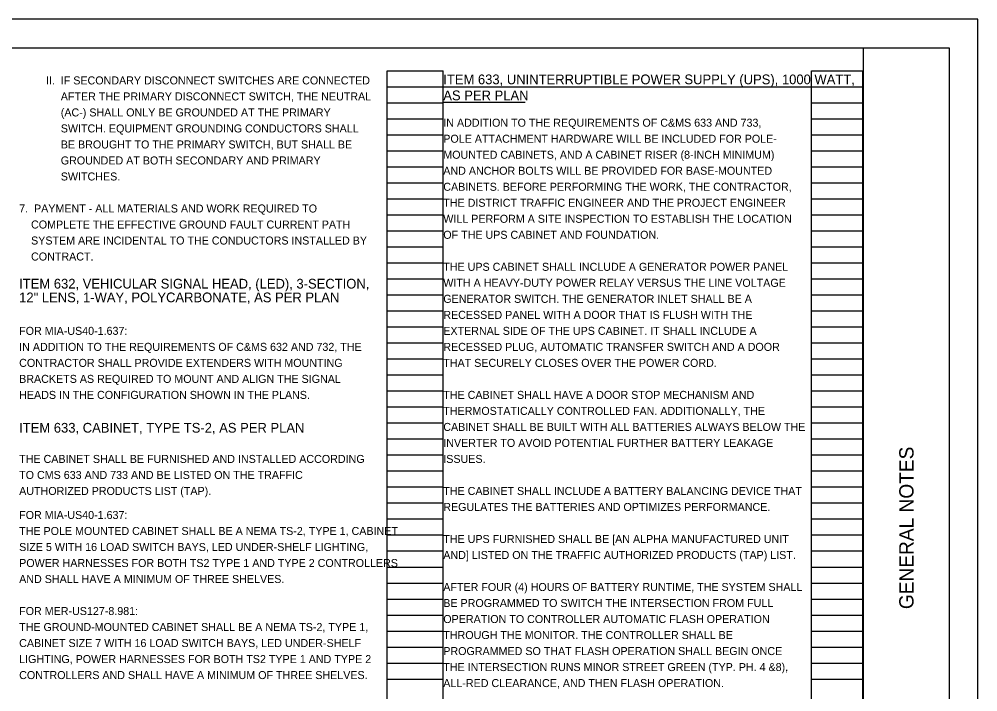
# Model space of a CAD drawing. Extents: x -57 to 90, y -15 to 48.
# Drawn here: x 72.92 to 89.69, y 35.74 to 47.51 of the extents above; entities that cross this region are included whole.
import ezdxf

# ---------------------------------------------------------------- set-up
doc = ezdxf.new("R2010")
doc.units = 0
for name, color, linetype in [('SH_Border', 7, 'Continuous'), ('SH_Cut_Line', 7, 'Continuous'), ('SH_Data', 7, 'Continuous'), ('SH_Text', 7, 'Continuous')]:
    doc.layers.add(name, color=color, linetype=linetype)

msp = doc.modelspace()

# ---------------------------------------------------------------- linework, layer by layer
at = {"layer": 'SH_Border'}
msp.add_line((87.688, 26.006), (87.688, 47.006), dxfattribs=at)
msp.add_lwpolyline([(57.188, 47.006), (89.188, 47.006), (89.188, 26.006), (57.188, 26.006)], close=True, dxfattribs=at)
at = {"layer": 'SH_Cut_Line'}
msp.add_lwpolyline([(55.688, 25.506), (89.688, 25.506), (89.688, 47.506), (55.688, 47.506)], close=True, dxfattribs=at)
at = {"layer": 'SH_Data'}
for p, q in [((79.356, 26.445), (79.356, 46.605)), ((79.356, 46.605), (80.336, 46.605)), ((80.336, 26.445), (80.336, 46.605)), ((86.776, 26.445), (86.776, 46.605)), ((86.776, 46.605), (87.676, 46.605)), ((87.676, 26.445), (87.676, 46.605)), ((79.356, 46.325), (80.336, 46.325)), ((86.776, 46.325), (87.676, 46.325)), ((79.356, 46.045), (80.336, 46.045)), ((86.776, 46.045), (87.676, 46.045)), ((79.356, 45.765), (80.336, 45.765)), ((86.776, 45.765), (87.676, 45.765)), ((79.356, 45.485), (80.336, 45.485)), ((86.776, 45.485), (87.676, 45.485)), ((79.356, 45.205), (80.336, 45.205)), ((86.776, 45.205), (87.676, 45.205)), ((79.356, 44.925), (80.336, 44.925)), ((86.776, 44.925), (87.676, 44.925)), ((79.356, 44.645), (80.336, 44.645)), ((86.776, 44.645), (87.676, 44.645)), ((79.356, 44.365), (80.336, 44.365)), ((86.776, 44.365), (87.676, 44.365)), ((79.356, 44.085), (80.336, 44.085)), ((86.776, 44.085), (87.676, 44.085)), ((79.356, 43.805), (80.336, 43.805)), ((86.776, 43.805), (87.676, 43.805)), ((79.356, 43.525), (80.336, 43.525)), ((86.776, 43.525), (87.676, 43.525)), ((79.356, 43.245), (80.336, 43.245)), ((86.776, 43.245), (87.676, 43.245)), ((79.356, 42.965), (80.336, 42.965)), ((86.776, 42.965), (87.676, 42.965)), ((79.356, 42.685), (80.336, 42.685)), ((86.776, 42.685), (87.676, 42.685)), ((79.356, 42.405), (80.336, 42.405)), ((86.776, 42.405), (87.676, 42.405)), ((79.356, 42.125), (80.336, 42.125)), ((86.776, 42.125), (87.676, 42.125)), ((79.356, 41.845), (80.336, 41.845)), ((86.776, 41.845), (87.676, 41.845)), ((79.356, 41.565), (80.336, 41.565)), ((86.776, 41.565), (87.676, 41.565)), ((79.356, 41.285), (80.336, 41.285)), ((86.776, 41.285), (87.676, 41.285)), ((79.356, 41.005), (80.336, 41.005)), ((86.776, 41.005), (87.676, 41.005)), ((79.356, 40.725), (80.336, 40.725)), ((86.776, 40.725), (87.676, 40.725)), ((79.356, 40.445), (80.336, 40.445)), ((86.776, 40.445), (87.676, 40.445)), ((79.356, 40.165), (80.336, 40.165)), ((86.776, 40.165), (87.676, 40.165)), ((79.356, 39.885), (80.336, 39.885)), ((86.776, 39.885), (87.676, 39.885)), ((79.356, 39.605), (80.336, 39.605)), ((86.776, 39.605), (87.676, 39.605)), ((79.356, 39.325), (80.336, 39.325)), ((86.776, 39.325), (87.676, 39.325)), ((79.356, 39.045), (80.336, 39.045)), ((86.776, 39.045), (87.676, 39.045)), ((79.356, 38.765), (80.336, 38.765)), ((86.776, 38.765), (87.676, 38.765)), ((79.356, 38.485), (80.336, 38.485)), ((86.776, 38.485), (87.676, 38.485)), ((79.356, 38.205), (80.336, 38.205)), ((86.776, 38.205), (87.676, 38.205)), ((79.356, 37.925), (80.336, 37.925)), ((86.776, 37.925), (87.676, 37.925)), ((79.356, 37.645), (80.336, 37.645)), ((86.776, 37.645), (87.676, 37.645)), ((79.356, 37.365), (80.336, 37.365)), ((86.776, 37.365), (87.676, 37.365)), ((79.356, 37.085), (80.336, 37.085)), ((86.776, 37.085), (87.676, 37.085)), ((79.356, 36.805), (80.336, 36.805)), ((86.776, 36.805), (87.676, 36.805)), ((79.356, 36.525), (80.336, 36.525)), ((86.776, 36.525), (87.676, 36.525)), ((79.356, 36.245), (80.336, 36.245)), ((86.776, 36.245), (87.676, 36.245)), ((79.356, 35.965), (80.336, 35.965)), ((86.776, 35.965), (87.676, 35.965))]:
    msp.add_line(p, q, dxfattribs=at)
at = {"layer": 'SH_Text'}
for p, q in [((80.336, 46.325), (87.45, 46.325)), ((80.336, 46.055), (81.771, 46.055))]:
    msp.add_line(p, q, dxfattribs=at)

# ---------------------------------------------------------------- texts
at = {"layer": 'SH_Data'}
msp.add_text('GENERAL NOTES', height=0.25, rotation=90, dxfattribs=at).set_placement((88.563, 37.188))
at = {"layer": 'SH_Text'}
for s, height, p in [('         II.  IF SECONDARY DISCONNECT SWITCHES ARE CONNECTED', 0.14, (72.916, 46.365)), ('ITEM 633, UNINTERRUPTIBLE POWER SUPPLY (UPS), 1000 WATT,', 0.17, (80.336, 46.368)), ('              AFTER THE PRIMARY DISCONNECT SWITCH, THE NEUTRAL', 0.14, (72.916, 46.085)), ('AS PER PLAN', 0.17, (80.336, 46.088)), ('              (AC-) SHALL ONLY BE GROUNDED AT THE PRIMARY', 0.14, (72.916, 45.805)), ('              SWITCH. EQUIPMENT GROUNDING CONDUCTORS SHALL', 0.14, (72.916, 45.525)), ('IN ADDITION TO THE REQUIREMENTS OF C&MS 633 AND 733, ', 0.14, (80.336, 45.625)), ('POLE ATTACHMENT HARDWARE WILL BE INCLUDED FOR POLE-', 0.14, (80.336, 45.345)), ('              BE BROUGHT TO THE PRIMARY SWITCH, BUT SHALL BE', 0.14, (72.916, 45.245)), ('MOUNTED CABINETS, AND A CABINET RISER (8-INCH MINIMUM) ', 0.14, (80.336, 45.065)), ('              GROUNDED AT BOTH SECONDARY AND PRIMARY', 0.14, (72.916, 44.965)), ('              SWITCHES.', 0.14, (72.916, 44.685)), ('AND ANCHOR BOLTS WILL BE PROVIDED FOR BASE-MOUNTED ', 0.14, (80.336, 44.785)), ('CABINETS. BEFORE PERFORMING THE WORK, THE CONTRACTOR, ', 0.14, (80.336, 44.505)), ('THE DISTRICT TRAFFIC ENGINEER AND THE PROJECT ENGINEER ', 0.14, (80.336, 44.225)), ('7.  PAYMENT - ALL MATERIALS AND WORK REQUIRED TO', 0.14, (72.916, 44.125)), ('    COMPLETE THE EFFECTIVE GROUND FAULT CURRENT PATH', 0.14, (72.916, 43.845)), ('WILL PERFORM A SITE INSPECTION TO ESTABLISH THE LOCATION ', 0.14, (80.336, 43.945)), ('OF THE UPS CABINET AND FOUNDATION.', 0.14, (80.336, 43.665)), ('    SYSTEM ARE INCIDENTAL TO THE CONDUCTORS INSTALLED BY', 0.14, (72.916, 43.565)), ('    CONTRACT.', 0.14, (72.916, 43.285)), ('THE UPS CABINET SHALL INCLUDE A GENERATOR POWER PANEL ', 0.14, (80.336, 43.105)), ('ITEM 632, VEHICULAR SIGNAL HEAD, (LED), 3-SECTION, ', 0.17, (72.916, 42.795)), ('WITH A HEAVY-DUTY POWER RELAY VERSUS THE LINE VOLTAGE ', 0.14, (80.336, 42.825)), ('12" LENS, 1-WAY, POLYCARBONATE, AS PER PLAN', 0.17, (72.916, 42.555)), ('GENERATOR SWITCH. THE GENERATOR INLET SHALL BE A ', 0.14, (80.336, 42.545)), ('RECESSED PANEL WITH A DOOR THAT IS FLUSH WITH THE ', 0.14, (80.336, 42.265)), ('FOR MIA-US40-1.637:', 0.14, (72.916, 41.985)), ('EXTERNAL SIDE OF THE UPS CABINET. IT SHALL INCLUDE A ', 0.14, (80.336, 41.985)), ('IN ADDITION TO THE REQUIREMENTS OF C&MS 632 AND 732, THE ', 0.14, (72.916, 41.705)), ('RECESSED PLUG, AUTOMATIC TRANSFER SWITCH AND A DOOR ', 0.14, (80.336, 41.705)), ('CONTRACTOR SHALL PROVIDE EXTENDERS WITH MOUNTING ', 0.14, (72.916, 41.425)), ('THAT SECURELY CLOSES OVER THE POWER CORD.', 0.14, (80.336, 41.425)), ('BRACKETS AS REQUIRED TO MOUNT AND ALIGN THE SIGNAL ', 0.14, (72.916, 41.145)), ('HEADS IN THE CONFIGURATION SHOWN IN THE PLANS. ', 0.14, (72.916, 40.865)), ('THE CABINET SHALL HAVE A DOOR STOP MECHANISM AND ', 0.14, (80.336, 40.865)), ('THERMOSTATICALLY CONTROLLED FAN. ADDITIONALLY, THE ', 0.14, (80.336, 40.585)), ('ITEM 633, CABINET, TYPE TS-2, AS PER PLAN', 0.17, (72.916, 40.275)), ('CABINET SHALL BE BUILT WITH ALL BATTERIES ALWAYS BELOW THE ', 0.14, (80.336, 40.305)), ('INVERTER TO AVOID POTENTIAL FURTHER BATTERY LEAKAGE ', 0.14, (80.336, 40.025)), ('THE CABINET SHALL BE FURNISHED AND INSTALLED ACCORDING', 0.14, (72.916, 39.745)), ('ISSUES.', 0.14, (80.336, 39.745)), ('TO CMS 633 AND 733 AND BE LISTED ON THE TRAFFIC', 0.14, (72.916, 39.465)), ('AUTHORIZED PRODUCTS LIST (TAP).', 0.14, (72.916, 39.185)), ('THE CABINET SHALL INCLUDE A BATTERY BALANCING DEVICE THAT ', 0.14, (80.336, 39.185)), ('REGULATES THE BATTERIES AND OPTIMIZES PERFORMANCE. ', 0.14, (80.336, 38.905)), ('FOR MIA-US40-1.637:', 0.14, (72.916, 38.765)), ('THE POLE MOUNTED CABINET SHALL BE A NEMA TS-2, TYPE 1, CABINET ', 0.14, (72.916, 38.485)), ('THE UPS FURNISHED SHALL BE [AN ALPHA MANUFACTURED UNIT ', 0.14, (80.336, 38.345)), ('SIZE 5 WITH 16 LOAD SWITCH BAYS, LED UNDER-SHELF LIGHTING, ', 0.14, (72.916, 38.205)), ('AND] LISTED ON THE TRAFFIC AUTHORIZED PRODUCTS (TAP) LIST.', 0.14, (80.336, 38.065)), ('POWER HARNESSES FOR BOTH TS2 TYPE 1 AND TYPE 2 CONTROLLERS ', 0.14, (72.916, 37.925)), ('AND SHALL HAVE A MINIMUM OF THREE SHELVES. ', 0.14, (72.916, 37.645)), ('AFTER FOUR (4) HOURS OF BATTERY RUNTIME, THE SYSTEM SHALL ', 0.14, (80.336, 37.505)), ('BE PROGRAMMED TO SWITCH THE INTERSECTION FROM FULL ', 0.14, (80.336, 37.225)), ('FOR MER-US127-8.981:', 0.14, (72.916, 37.085)), ('OPERATION TO CONTROLLER AUTOMATIC FLASH OPERATION ', 0.14, (80.336, 36.945)), ('THE GROUND-MOUNTED CABINET SHALL BE A NEMA TS-2, TYPE 1,', 0.14, (72.916, 36.805)), ('THROUGH THE MONITOR. THE CONTROLLER SHALL BE ', 0.14, (80.336, 36.665)), ('CABINET SIZE 7 WITH 16 LOAD SWITCH BAYS, LED UNDER-SHELF', 0.14, (72.916, 36.525)), ('PROGRAMMED SO THAT FLASH OPERATION SHALL BEGIN ONCE ', 0.14, (80.336, 36.385)), ('LIGHTING, POWER HARNESSES FOR BOTH TS2 TYPE 1 AND TYPE 2', 0.14, (72.916, 36.245)), ('THE INTERSECTION RUNS MINOR STREET GREEN (TYP. PH. 4 &8), ', 0.14, (80.336, 36.105)), ('CONTROLLERS AND SHALL HAVE A MINIMUM OF THREE SHELVES.', 0.14, (72.916, 35.965)), ('ALL-RED CLEARANCE, AND THEN FLASH OPERATION. ', 0.14, (80.336, 35.825))]:
    msp.add_text(s, height=height, dxfattribs=at).set_placement(p)

doc.saveas('drawing.dxf')
